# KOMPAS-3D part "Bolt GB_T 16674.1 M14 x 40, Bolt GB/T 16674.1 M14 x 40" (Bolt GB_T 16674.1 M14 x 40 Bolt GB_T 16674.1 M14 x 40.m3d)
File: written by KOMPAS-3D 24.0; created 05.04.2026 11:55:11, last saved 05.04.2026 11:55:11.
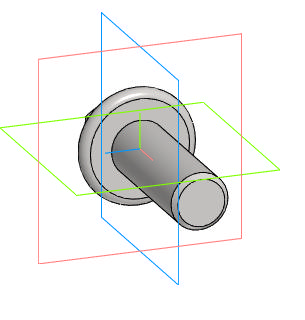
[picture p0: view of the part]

Document properties: Автор: R2D2; Полное имя файла: E:\Работа\Зайцев\Аксессуары для пневмоприводов\Ручной дублер DN.ru\MON4-1200-T54-ISO Ручной дублер DN.ru\исходные материалы\Bolt GB_T 16674.1 M14 x 40 Bolt GB_T 16674.1 M14 x 40.m3d

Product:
- Body: Solid1  | qty 1
- Part/product: Bolt GB_T 16674.1 M14 x 40  | designation Bolt GB/T 16674.1 M14 x 40
    Комментарий: Hexagon  bolts with flang - Small series
    additional columns: Сталь, мягкая

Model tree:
1. Solid1  (labels: Solid1)

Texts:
  Bolt GB/T 16674.1 M14 x 40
